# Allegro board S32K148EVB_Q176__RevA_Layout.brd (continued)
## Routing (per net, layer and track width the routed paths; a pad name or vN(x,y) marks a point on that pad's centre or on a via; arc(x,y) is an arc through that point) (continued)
PTA19/FTM4_CH1/LPUART1_RX/LPSPI: length 12.1
  TOP w0.16: U8.2 v1(78.8,67.57)
  L3_INT_1 w0.191: J6.13 81.24,71.49 78.8,69.05
  L3_INT_1 w0.203: 78.8,69.05 v1(78.8,67.57)
PTA20/FTM4_CH2/LPSPI1_SIN: length 18.1
  TOP w0.16: U8.3 v1(78.3,68.04)
  L3_INT_1 w0.191: J6.15 80.13,81.4 80.13,76.71 80.68,76.17 80.68,74.81 77.88,72.01 77.88,69.13 77.97,69.05
  L3_INT_1 w0.203: 77.97,69.05 78.3,68.71 v1(78.3,68.04)
PTA21/FTM4_CH3/FXIO_D0/LPSPI1_P: length 21.1
  TOP w0.16: U8.6 v1(76.8,67.57)
  L3_INT_1 w0.191: 80.77,69.05 80.8,69.07 81.01,69.07 82.65,70.71 82.65,81.37 J6.12
  L3_INT_1 w0.203: 80.77,69.05 80.1,68.37 80.1,68.16 79.03,67.09 77.28,67.09 v1(76.8,67.57)
PTA22/FTM4_CH4/FXIO_D1/LPSPI1_P: length 25.5
  TOP w0.16: U8.9 v1(75.3,68.04)
  L3_INT_1 w0.191: J6.9 85.21,81.4 85.21,76.97 85.48,76.7 85.48,73.04 81.49,69.05
  L3_INT_1 w0.203: v1(75.3,68.04) 75.3,67.39 75.95,66.74 79.18,66.74 80.45,68.01 80.45,68.23 80.95,68.72 81.16,68.72 81.49,69.05
PTA23/FTM4_CH6/FXIO_D2: length 29
  TOP w0.16: U8.13 v1(73.3,68.04)
  L3_INT_1 w0.191: J6.6 87.43,81.08 87.43,74.49 81.99,69.05
  L3_INT_1 w0.203: v1(73.3,68.04) 73.3,67.39 74.31,66.38 79.33,66.38 80.81,67.87 80.81,68.08 81.09,68.36 81.31,68.36 81.99,69.05
PTA24/FTM4_CH7/FXIO_D3: length 31.9
  TOP w0.16: U8.16 v1(71.79,67.57)
  L3_INT_1 w0.191: J6.3 90.29,81.4 90.29,75.28 86.11,71.1 86,71.1 85.72,70.82 85.72,70.71 83.93,68.92
  L3_INT_1 w0.203: v1(71.79,67.57) 73.34,66.03 81.04,66.03 83.93,68.92
PTA25/FTM5_CH0: length 81.2
  TOP w0.16: U8.17 v1(71.29,68.04) ; U7.10 v1(72.79,63.24)
  L6_INT_2 w0.191: 52.74,67.58 51.68,67.58 42.94,76.32 41.18,76.32 40.52,76.97 40.52,78.87 J2.2 ; v1(40.53,51.62) 40.53,52.45 37.71,55.27 37.71,61.36 39.18,62.82 v1(40.12,62.82)
  L6_INT_2 w0.203: v1(71.29,68.04) 71.29,67.39 70.64,66.74 56.32,66.74 55.94,67.12 53.21,67.12 52.74,67.58
  BOTTOM w0.16: v1(71.29,68.04) 71.29,66.07 71.78,65.58 71.78,65.33 72.79,64.32 v1(72.79,63.24)
  BOTTOM w0.406: R552.1 v1(40.53,51.62) ; J2.2 42.84,78.75 42.84,76.43 41.03,74.63 41.03,63.74 v1(40.12,62.82)
PTA26/FTM5_CH1/LPSPI1_PCS0: length 144.7
  TOP w0.16: U8.26 v1(66.79,67.57) ; U7.19 v1(68.29,62.77)
  TOP w0.406: v1(57.65,20.03) 57.65,21.24 56.83,22.06 R283.1
  L3_INT_1 w0.191: v1(80.4,32.7) 80.4,33.04 81.65,34.29 81.65,36.44 83.34,38.14 83.34,40.68 81.26,42.76 81.26,52.47 79.65,54.08 79.65,55.56 73.8,61.4 69.66,61.4 v1(68.29,62.77) ; v1(26.48,32.15) 26.48,42.42 26.83,42.76 26.83,43.16 26.48,43.51 26.48,45.6 26.08,46 26.08,46.08 v1(25.74,46.42)
  L6_INT_2 w0.191: v1(26.48,32.15) 26.48,21.77 28.35,19.9 39.08,19.9 39.64,20.46 57.21,20.46 v1(57.65,20.03)
  BOTTOM w0.16: v1(68.29,62.77) 68.29,64.73 66.79,66.23 v1(66.79,67.57)
  BOTTOM w0.191: v1(80.4,32.7) 77.48,29.78 77.48,25.36 72.15,20.03 v1(57.65,20.03)
  BOTTOM w0.203: R564.1 26.05,46.64 25.82,46.42 v1(25.74,46.42)
PTA26/FTM5_CH1/LPSPI1_PCS0_LS: length 9.6
  TOP w0.406: v1(29.81,56.59) R149.1
  TOP w0.508: v1(29.81,56.59) 29.78,56.61 29.73,56.61 29.49,56.86 TP17.1
  BOTTOM w0.203: U507.6 26.56,50.84 27.01,51.29 27.37,51.29 29.81,53.73 v1(29.81,56.59)
PTA27/FTM5_CH2/LPSPI1_SOUT/LP_1: length 4.9
  TOP w0.406: R177.1 30.29,53.4 TP22.1 31.43,53.4 v1(31.94,53.91)
  BOTTOM w0.203: U506.6 33.29,53.37 32.75,53.91 v1(31.94,53.91)
PTA27/FTM5_CH2/LPSPI1_SOUT/LPUA: length 93.6
  TOP w0.16: U7.22 v1(66.79,63.24) ; U8.29 v1(65.29,68.04)
  L3_INT_1 w0.191: v1(34.73,48.85) 35.21,48.85 35.78,49.42 37.42,49.42 39.3,51.3 39.3,51.97 40.85,53.52 42.05,53.52 46.55,58.02 v1(46.77,58.02)
  L6_INT_2 w0.191: J4.6 51.87,25.52 49.1,25.52 47.97,26.65 47.97,28.43 45.81,30.6 35.92,30.6 33.01,33.51 32.56,33.51 30.7,35.38 29.14,36.93 29.14,42.97 34.4,48.23 34.4,48.52 v1(34.73,48.85) ; v1(46.77,58.02) 48.59,58.02 52.27,61.71 52.74,61.71
  L6_INT_2 w0.203: v1(66.79,63.24) 66.79,62.59 65.35,61.15 60.85,61.15 60.38,61.62 59.36,61.62 59.19,61.45 54.45,61.45 54.2,61.71 52.74,61.71
  BOTTOM w0.16: v1(66.79,63.24) 66.79,64.7 65.29,66.2 v1(65.29,68.04)
  BOTTOM w0.203: v1(34.73,48.85) R555.1
PTA28/FTM5_CH3/LPSPI1_SCK/LPU_1: length 10.2
  TOP w0.406: R150.1 29.91,54.82 30.57,55.48 v1(30.57,55.89) 30.92,55.89 31.15,56.12 TP21.1
  BOTTOM w0.203: v1(30.57,55.89) 30.23,55.55 30.23,53.57 27.57,50.91 27.18,50.91 26.96,50.7 U507.7
PTA28/FTM5_CH3/LPSPI1_SCK/LPUAR: length 126.8
  TOP w0.16: U8.31 v1(64.29,68.04) ; U7.24 v1(65.79,63.24)
  L6_INT_2 w0.191: J4.9 54.11,22.36 43.32,22.36 42.03,23.65 42.03,26.75 40.83,27.95 35.19,27.95 34.41,28.73 34.41,31.15 32.69,32.87 32.31,32.87 30.43,34.74 27.41,37.76 v1(27.41,42.24) 27.41,43.18 27.72,43.48 28.75,43.48 32.09,46.82 32.09,51.98 31.77,52.3 31.74,52.3 30.41,53.63 29.13,53.63 27.22,55.54 27.22,56.93 29.58,59.29 30.65,59.29 32.31,57.63 33.53,57.63 39.2,63.31 41.19,63.31 41.31,63.19 50.68,63.19 v1(51.09,63.6) ; v1(64.29,68.04) 62.94,69.4 61.58,69.4 61.19,69.78 57.79,69.78 57.13,69.12 54.72,69.12 54.51,69.34 52.83,69.34 v1(51.17,71)
  BOTTOM w0.16: v1(65.79,63.24) 65.79,64.75 64.29,66.25 v1(64.29,68.04)
  BOTTOM w0.191: v1(51.17,71) 51.62,70.55 51.62,64.13 v1(51.09,63.6)
  BOTTOM w0.406: v1(27.41,42.24) 27.41,44.2 27.52,44.31 R563.1
PTA29/FTM5_CH4/LPUART2_TX/LPS_1: length 5.5
  TOP w0.406: v1(33.69,53.67) 33.66,53.71 33.08,53.71 32.27,54.52 TP25.1 30.39,54.52 R154.1
  BOTTOM w0.203: U506.7 v1(33.69,53.67)
PTA29/FTM5_CH4/LPUART2_TX/LPSPI: length 113.2
  TOP w0.16: U7.26 v1(64.79,63.24) ; U8.33 v1(63.29,68.04)
  L3_INT_1 w0.191: v1(36.32,51.34) 36.66,51.68 36.66,53.25 36.09,53.83 36.09,54.69 36.37,54.97 37.71,54.97 37.86,54.82 38.65,54.82 39.16,55.33 41.61,55.33 46.29,60.01 v1(51.24,60.01)
  L6_INT_2 w0.191: v1(36.32,51.34) 33.95,48.97 33.95,48.23 28.82,43.1 28.82,36.8 30.19,35.43 32.43,33.2 32.82,33.2 35.73,30.28 43.58,30.28 44.25,29.61 44.25,23.96 45.54,22.67 53.89,22.67 54.73,23.52 54.73,24.53 55.39,25.19 57.28,25.19 J4.12 ; 52.74,68.99 52.29,68.99 v1(51.14,70.14) ; 57.55,69.05 57.97,69.47 61.06,69.47 61.48,69.05
  L6_INT_2 w0.203: 57.55,69.05 57.25,68.74 54.61,68.74 54.36,68.99 52.74,68.99 ; 61.48,69.05 62.28,69.05 v1(63.29,68.04)
  BOTTOM w0.16: v1(63.29,68.04) 63.29,66.29 64.79,64.79 v1(64.79,63.24)
  BOTTOM w0.203: R554.1 36.74,51.04 36.54,51.24 36.54,51.34 v1(36.32,51.34)
  BOTTOM w0.406: v1(51.24,60.01) 51.24,60.59 50.51,61.33 50.51,65.4 51.14,66.04 v1(51.14,70.14)
PTA30/FTM5_CH5: length 54.6
  TOP w0.16: U8.34 v1(62.79,67.57) ; U7.27 v1(64.29,62.77)
  L3_INT_1 w0.191: 62.79,69.05 62.79,70.79 64.89,72.89 64.89,82.65 63.92,83.62 45,83.62 v1(43.69,82.31)
  L3_INT_1 w0.203: v1(62.79,67.57) 62.79,69.05
  L6_INT_2 w0.191: v1(43.69,82.31) 43.69,81.39 43.21,80.92 42.24,80.92 42.08,81.08 41.16,81.08 40.19,80.11 40.19,78.54 J2.4
  BOTTOM w0.16: v1(62.79,67.57) 62.79,66.32 64.29,64.81 v1(64.29,62.77)
PTA31/FTM5_CH6: length 40.1
  TOP w0.16: U7.33 v1(61.29,62.77) ; U8.40 v1(59.79,67.57)
  L3_INT_1 w0.191: v1(44.33,82.07) 45.01,81.4 48.81,81.4 49.65,80.56 49.65,75.4 50.7,74.36 53.43,74.36 55.97,71.82
  L3_INT_1 w0.203: v1(59.79,67.57) 59.79,70.26 58.23,71.82 55.97,71.82
  L6_INT_2 w0.191: v1(44.33,82.07) 44.33,80.14 J2.1
  BOTTOM w0.16: v1(59.79,67.57) 59.79,65.99 61.29,64.49 v1(61.29,62.77)
PTB0/SBC_LPSPI0_PCS0: length 92
  TOP w0.16: U7.78 v1(62.29,44.59)
  TOP w0.203: v1(61.8,39.78) 61.79,39.8 61.79,40.98
  BOTTOM w0.16: v1(61.8,39.78) 61.8,40.26 62.29,40.75 v1(62.29,44.59)
  BOTTOM w0.191: J2.7 37.64,78.53 37.64,82.96 36.69,83.91 26.22,83.91 24.96,82.65 24.96,71.53 39.33,57.16 39.46,57.16 46.44,50.18 46.44,48.83 46.84,48.43 46.84,46.88 52.72,41.01 54.22,41.01 57.11,38.11 59.77,38.11 59.78,38.12 60.7,38.12 60.71,38.11 60.75,38.11 61.79,39.15 61.79,39.3 61.8,39.31 v1(61.8,39.78)
PTB1/LPSPI0_SOUT: length 67.2
  TOP w0.16: 61.29,40.98 61.29,39.79 61.29,39.78 v1(61.29,39.32) ; U7.77 v1(61.79,44.12)
  L3_INT_1 w0.191: 52.74,69.05 51.56,69.05 43.12,77.49 43.12,80.02 42.07,81.07 36.08,81.07 35.11,80.09 35.11,78.54 J2.10
  L3_INT_1 w0.203: v1(61.79,44.12) 61.31,43.64 59.09,43.64 58.15,44.58 58.15,65.1 55.77,67.47 54.43,67.47 52.85,69.05 52.74,69.05
  BOTTOM w0.16: v1(61.29,39.32) 61.29,40.33 61.79,40.83 v1(61.79,44.12)
PTB2/LPSPI0_SCK: length 76.1
  TOP w0.16: U7.68 v1(58.98,46.93) ; U8.78 v1(54.65,47.93)
  L6_INT_2 w0.191: J2.16 31.36,74.99 38.44,74.99 38.5,74.93 v1(38.98,74.93)
  BOTTOM w0.16: v1(58.98,46.93) 57.99,47.93 v1(54.65,47.93)
  BOTTOM w0.191: v1(38.98,74.93) 39.31,75.27 39.31,75.46 40.51,76.65 40.51,82.97 41.16,83.62 48.68,83.62 49.33,82.97 49.33,76.84 50.32,75.85 51.36,75.85 51.76,75.45 51.76,74.83 50.34,73.4 50.34,66.46 49.75,65.88 49.75,60.96 50.36,60.36 50.36,54.93 52.95,52.33 52.95,48.99 54.01,47.93 v1(54.65,47.93)
PTB3/LPSPI0_SIN: length 72.4
  TOP w0.16: U8.73 v1(54.18,50.43) ; U7.63 v1(59.45,49.43)
  L6_INT_2 w0.191: v1(38.44,75.47) 38.11,75.8 33.08,75.8 J2.13
  BOTTOM w0.16: v1(54.18,50.43) 55.54,50.43 56.54,49.43 v1(59.45,49.43)
  BOTTOM w0.191: 52.11,74.56 52.11,75.56 51.49,76.17 50.45,76.17 49.65,76.97 49.65,83.1 48.81,83.94 41.03,83.94 40.19,83.1 40.19,76.87 39.12,75.8 38.78,75.8 v1(38.44,75.47)
  BOTTOM w0.203: 52.11,74.56 50.66,73.11 50.66,66.33 50.08,65.74 50.08,61.1 50.68,60.5 50.68,55.14 53.33,52.48 53.33,51.09 53.99,50.43 v1(54.18,50.43)
PTB4/MII_RMII_MDIO: length 104
  TOP w0.406: R268.2 v1(39.18,32.56) ; R46.2 103.71,73.62 103.31,73.23 v1(103.29,73.23)
  L6_INT_2 w0.191: v1(103.29,73.23) 103.77,73.23 107.89,69.1 107.89,56.66 102.17,50.93 100.09,50.93 99.63,50.47 99.63,45.6 85.25,31.22 78.39,31.22 78.14,31.47 60.54,31.47 60.46,31.55 57.16,31.55 56.95,31.76 51.49,31.76 51.09,31.36 39.9,31.36 39.18,32.08 v1(39.18,32.56)
PTB4/MII_RMII_MDIO/QSPI_B_IO0: length 49.5
  TOP w0.16: U7.41 v1(59.45,60.43) ; U8.49 v1(54.18,62.44)
  TOP w0.406: R227.1 36.06,42.25 36.03,42.27 v1(34.89,42.27)
  L3_INT_1 w0.191: 52.74,62.44 43.38,62.44 39.17,58.23 36.35,58.23 34.99,56.88 34.99,54.02 35.78,53.23 35.78,52.24 33.79,50.25 33.79,42.9 34.41,42.27 v1(34.89,42.27)
  L3_INT_1 w0.203: v1(54.18,62.44) 52.74,62.44
  BOTTOM w0.16: v1(59.45,60.43) 57.44,60.43 55.44,62.44 v1(54.18,62.44)
PTB4/MII_RMII_MDIO/QSPI_B_IO0_1: length 4.1
  TOP w0.279: R268.1 38.7,34.81 v1(38.7,35.41) 38.7,35.93 38.84,36.07 38.84,36.08 38.84,36.08 U14.2
  BOTTOM w0.279: v1(38.7,35.41) 38.7,34.81 R268.1
PTB4/MII_RMII_MDIO/QSPI_B_IO0__: length 3.3
  TOP w0.279: v1(37.98,41.39) 38.35,41.02 38.39,41.02 38.84,40.57 U14.13
  TOP w0.406: v1(37.98,41.39) 37.96,41.39 38.04,41.46 R227.2
  BOTTOM w0.279: v1(37.98,41.39) 37.96,41.39 38.04,41.47 38.04,41.85 R572.2
PTB5/ENET_MII_RMII_MDC: length 104.9
  TOP w0.279: U22.2 65.75,34.52 65.76,34.5 65.76,33.98 66,33.74 v1(66.52,33.74) R273.2
  TOP w0.406: R38.2 103.52,74.64 102.6,73.72 v1(102.6,73.14)
  L6_INT_2 w0.191: v1(66.52,33.74) 68.52,33.74 68.99,34.22 78.8,34.22 79.32,33.7 79.71,33.7 80.81,34.8 83.44,34.8 83.45,34.8 84.11,34.8 84.39,35.08 84.39,35.74 91.47,42.82 91.47,46.55 92.72,47.81 92.72,47.83 98.52,53.62 100.17,53.62 101.01,54.46 101.01,54.59 104.06,57.64 104.06,60.77 102.51,62.32 102.51,64.01 103.16,64.66 103.16,67.78 102.6,68.34 102.6,68.5 102.51,68.59 101.64,68.59 101.55,68.68 101.55,68.81 101.64,68.91 102.51,68.91 102.6,69 102.6,69.13 102.51,69.23 101.64,69.23 101.55,69.32 101.55,69.45 101.64,69.54 102.51,69.54 102.6,69.64 102.6,69.77 102.51,69.86 101.64,69.86 101.55,69.95 101.55,70.08 101.64,70.18 102.51,70.18 102.6,70.27 102.6,70.59 102.51,70.68 101.22,70.68 101.13,70.59 101.13,70.13 101.04,70.04 100.91,70.04 100.81,70.13 100.81,70.59 100.72,70.68 100.59,70.68 100.5,70.59 100.5,70.13 100.4,70.04 100.27,70.04 100.18,70.13 100.18,70.59 100.09,70.68 99.95,70.68 99.86,70.59 99.86,70.13 99.77,70.04 99.64,70.04 99.54,70.13 99.54,70.59 99.45,70.68 98.68,70.68 98.59,70.77 98.59,70.91 98.68,71 99.41,71 99.51,71.09 99.51,71.88 99.6,71.97 99.73,71.97 99.82,71.88 99.82,71.09 99.92,71 100.99,71 101.08,71.09 101.08,71.41 100.99,71.5 100.33,71.5 100.23,71.6 100.23,71.73 100.33,71.82 100.99,71.82 101.08,71.91 101.08,72.04 100.99,72.14 100.33,72.14 100.23,72.23 100.23,72.36 100.33,72.45 100.99,72.45 101.08,72.55 101.08,73.25 101.17,73.34 101.31,73.34 101.4,73.25 101.4,71.09 101.49,71 101.62,71 101.72,71.09 101.72,73.25 101.81,73.34 101.94,73.34 102.03,73.25 102.03,71.09 102.13,71 102.51,71 102.6,71.09 102.6,71.3 102.7,71.4 103.04,71.4 103.13,71.49 103.13,71.62 103.04,71.71 102.7,71.71 102.6,71.81 102.6,71.94 102.7,72.03 103.04,72.03 103.13,72.12 103.13,72.26 103.04,72.35 102.7,72.35 102.6,72.44 v1(102.6,73.14)
PTB5/MII_RMII_MDC: length 89.2
  TOP w0.16: U8.48 v1(54.65,62.94) ; U7.40 v1(58.98,60.93)
  L3_INT_1 w0.191: v1(54.65,62.94) 54.65,63.06 54.15,63.56 51.74,63.56 v1(51.09,62.91)
  L6_INT_2 w0.191: v1(58.64,32.37) 57.52,32.37 57.12,32.77 56.7,32.77 56.01,32.08 51.36,32.08 50.96,31.68 40.4,31.68 39.66,32.43 39.66,32.76 39.38,33.04 36.63,33.04 35.18,34.49 32.48,34.49 29.78,37.2 29.78,41.11 35.36,46.7 38.73,46.7 40.77,48.73 40.77,50.1 41,50.33 41,52.43 39.68,53.75 39.68,54.89 39.4,55.17 39.38,55.17 38.63,55.92 38.63,60.75 40.14,62.27 50.44,62.27 v1(51.09,62.91)
  BOTTOM w0.16: v1(58.98,60.93) 57.42,60.93 55.41,62.94 v1(54.65,62.94)
  BOTTOM w0.406: R604.1 v1(58.64,32.37)
PTB5/MII_RMII_MDC__A: length 3.6
  TOP w0.279: v1(60.6,33.93) 60.6,34.1 60.83,34.34 60.83,34.43 60.92,34.52 U22.13
  BOTTOM w0.406: R604.2 60.19,33.93 v1(60.6,33.93) 60.99,33.54 R603.2
PTB6_XTAL: length 16.5
  TOP w0.16: U8.25 v1(67.29,68.04) ; U7.18 v1(68.79,63.24)
  TOP w0.229: C3.1 Y1.2 66.53,71 67.02,70.51 R64.2 ; R64.2 R76.2 67.02,68.32 v1(67.29,68.04) ; R64.2 66.26,70.32 66,70.06 R76.1
  BOTTOM w0.16: v1(68.79,63.24) 68.79,64.73 67.29,66.23 v1(67.29,68.04)
PTB7_EXTAL: length 17.2
  TOP w0.16: U8.24 v1(67.79,67.57) ; U7.17 v1(69.29,62.77)
  TOP w0.229: R78.1 69.05,69.96 68.69,70.32 R64.1 ; R64.1 R78.2 68.03,68.74 67.79,68.5 v1(67.79,67.57) ; R64.1 68.53,70.81 Y1.1 C4.1
  BOTTOM w0.16: v1(67.79,67.57) 67.79,66.29 69.29,64.79 v1(69.29,62.77)
PTB8/FTM3_CH0/SAI1_BCLK: length 64.7
  TOP w0.16: U8.136 v1(82.91,44.42) ; U7.111 v1(78.1,45.93)
  TOP w0.406: R318.1 55.31,13.65 63.18,13.65 J5.4
  L3_INT_1 w0.203: v1(78.1,45.93) 78.58,45.93 78.96,45.56 78.96,41.8 80.57,40.18 80.57,39.19 79.07,37.69 79.07,35.11 78.6,34.64 77.51,34.64 72.5,29.63 72.5,28.71 73.36,27.85 74.94,27.85 J5.4
  BOTTOM w0.16: v1(82.91,44.42) 80.72,44.42 79.21,45.93 v1(78.1,45.93)
PTB9/FTM3_CH1/LPI2C0_SCLS: length 107.2
  TOP w0.16: U8.133 82.31,42.92 82.33,42.9 v1(82.8,42.9) ; U7.109 v1(78.1,44.93)
  TOP w0.203: v1(82.8,42.9) 83.52,42.9 83.55,42.92 83.93,42.92
  TOP w0.406: 83.93,42.92 84.76,42.92 86.93,45.1 89.32,45.1 89.73,45.5 v1(89.73,50.12) R192.1 ; R319.1 v1(55.59,12.35)
  L3_INT_1 w0.191: v1(55.59,12.35) 56.05,11.9 62.1,11.9 75.29,25.08 76.18,25.08 77.27,26.17 77.27,27.22 78.11,28.06 79.16,28.06 79.81,28.71 79.81,29.93 84.84,34.95 84.84,36.62 84.35,37.12 84.35,37.72 84.51,37.88 84.51,42.03 83.93,42.61
  L3_INT_1 w0.203: v1(82.8,42.9) 83.64,42.9 83.93,42.61
  L6_INT_2 w0.191: J6.10 85.81,75.4 v1(91.22,75.4)
  BOTTOM w0.16: v1(78.1,44.93) 80.21,42.82 82.25,42.82 82.33,42.9 v1(82.8,42.9)
  BOTTOM w0.406: v1(91.22,75.4) 90.51,74.69 90.51,53.07 89.17,51.73 89.17,50.68 v1(89.73,50.12)
PTB10/FTM3_CH2/LPI2C0_SDAS: length 153.3
  TOP w0.16: 78.8,40.98 v1(78.8,39.32) ; U7.108 77.29,43.99 77.46,44.16 77.46,44.16 v1(77.48,44.16)
  TOP w0.406: R315.1 v1(45.43,12.14) ; R187.1 v1(89.75,51.14)
  L3_INT_1 w0.191: v1(45.43,12.14) 46.12,12.83 52.32,12.83 53.57,11.58 63.7,11.58 64.93,12.81 66.82,12.81 67.77,11.85 81.19,11.85 90.28,20.95 90.28,28.56 90.29,28.58 90.29,29.76 90.28,29.77 90.28,50.61 v1(89.75,51.14)
  L6_INT_2 w0.191: v1(89.75,51.14) 90.2,50.69 90.2,48.43 89.21,47.44 89.21,43.9 85.29,39.99 83.93,39.99
  L6_INT_2 w0.203: v1(78.8,39.32) 79.14,38.98 79.67,38.98 80.68,39.99 83.93,39.99
  BOTTOM w0.16: v1(78.8,39.32) 78.8,42.83 v1(77.48,44.16)
  BOTTOM w0.406: v1(89.75,51.14) 91.73,53.12 91.73,70.95 92.62,71.84 92.62,80.47 91.91,81.19 85.82,81.19 85.1,80.47 85.1,78.65 J6.7
PTB11/FTM3_CH3/LPI2C0_HREQ: length 86.9
  TOP w0.16: U7.107 v1(76.79,44.15) ; 77.3,40.98 v1(77.3,39.79)
  L3_INT_1 w0.191: J2.17 27.82,78.87 27.82,76.97 31.56,73.24 45.11,73.24 52.69,65.66 52.74,65.66
  L3_INT_1 w0.203: v1(76.79,44.15) 76.45,43.81 76.45,43.78 74.53,41.86 58.35,41.86 56.37,43.85 56.37,64.36 55.07,65.66 52.74,65.66
  BOTTOM w0.16: v1(77.3,39.79) 77.3,43.62 77.12,43.8 77.12,43.83 v1(76.79,44.15)
PTB12/FTM0_CH0/FTM3_FLT2/CAN2_R: length 95.5
  TOP w0.16: 72.8,40.98 v1(72.8,39.32) ; U7.98 v1(72.29,44.59)
  L3_INT_1 w0.191: J2.29 20.17,78.55 26.52,78.55 27.8,79.84 27.8,80.41 28.46,81.07 29.37,81.07 30.35,80.09 30.35,76.99 33.76,73.57 45.23,73.57 51.94,66.86 52.74,66.86
  L3_INT_1 w0.203: v1(72.29,44.59) 72.29,43.94 70.57,42.22 58.5,42.22 56.72,43.99 56.72,64.51 55.21,66.02 53.59,66.02 52.74,66.86
  BOTTOM w0.16: v1(72.29,44.59) 72.29,40.91 72.8,40.41 v1(72.8,39.32)
PTB13/FTM0_CH1/FTM3_FLT1/CAN2_T: length 83.1
  TOP w0.16: U7.97 v1(71.79,44.12) ; 72.29,40.98 v1(72.29,39.79)
  BOTTOM w0.16: 71.79,40.29 v1(72.29,39.79)
  BOTTOM w0.191: J2.26 22.41,78.86 22.41,75.1 23.18,74.32 23.18,72.86 39.2,56.84 39.31,56.84 46.11,50.04 46.11,48.7 46.52,48.29 ; v1(72.29,39.79) 72.29,39.01 72.62,38.68 72.62,38.47 72.66,38.43 72.66,38.04 72.62,38 72.62,37.93 72.32,37.62 65.44,37.62 64.94,37.11 63.05,37.11 62.76,37.41 60.96,37.41 60.57,37.8 59.91,37.8 59.9,37.79 56.94,37.79 54.08,40.65
  BOTTOM w0.203: 46.52,48.29 46.52,46.72 52.59,40.65 54.08,40.65 ; v1(71.79,44.12) 71.79,40.29
PTB14/FTM0_CH2/LPSPI1_SCK/ADC1_: length 32.6
  TOP w0.16: 71.29,40.98 v1(71.29,39.79) ; U7.96 v1(71.29,44.59)
  TOP w0.203: v1(71.29,39.79) 71.29,39.02 71.59,38.72 73.16,38.72
  TOP w0.406: J5.15 88.02,32.55 83.64,32.55 80.17,36.03 75.86,36.03 73.16,38.72
  BOTTOM w0.16: v1(71.29,39.79) 71.29,40.25 71.29,40.25 v1(71.29,44.59)
PTB15/FTM0_CH3/LPSPI1_SIN/ADC1_: length 37.3
  TOP w0.16: 70.79,40.98 v1(70.79,39.32) ; U7.95 v1(70.79,44.12)
  TOP w0.203: v1(70.79,39.32) 70.79,38.83 71.01,38.62
  TOP w0.406: J5.17 92.7,27.93 88.4,27.93 88.37,27.95 88.36,27.95 87.64,28.66 87.64,28.68 87.59,28.73 87.59,30.26 86.53,31.33 78.17,31.33 71.31,38.19 71.31,38.32 71.01,38.62
  BOTTOM w0.16: v1(70.79,39.32) 70.79,39.78 70.79,39.78 v1(70.79,44.12)
PTB16: length 10.2
  TOP w0.16: U7.94 v1(70.29,44.61)
  TOP w0.203: 70.29,40.98 v1(70.29,39.79)
  BOTTOM w0.16: v1(70.29,44.61) 70.29,40.25 70.29,40.25 v1(70.29,39.79)
  BOTTOM w0.203: 70.5,38.62 70.5,38.93 70.29,39.14 v1(70.29,39.79)
  BOTTOM w0.406: v1(70.29,44.61) 70.27,44.64 R634.2 ; 70.5,38.62 70.5,38.31 R635.2
PTB16/FTM0_CH4/LPSPI1_SOUT/ADC1: length 31.4
  TOP w0.203: v1(81.8,38.82) 81.8,38.62
  TOP w0.406: J5.19 93.76,31.89 90.29,31.89 89.07,33.11 83.97,33.11 81.88,35.2 81.88,38.26 81.8,38.34 81.8,38.62
  L6_INT_2 w0.191: 73.04,38.62 72.66,38.24 v1(72.19,38.24)
  L6_INT_2 w0.203: v1(81.8,38.82) 81.6,38.62 73.05,38.62 73.04,38.62
  BOTTOM w0.406: R635.1 v1(72.19,38.24)
PTB17/FTM0_CH5/LPSPI1_PCS3/FTM5: length 116.9
  TOP w0.16: U7.93 v1(69.79,44.12) ; 69.29,40.98 v1(69.29,39.32)
  TOP w0.406: v1(69.38,30.92) 69.79,30.51 69.79,22.95 65.87,19.04 v1(65.29,19.04) ; R287.1 v1(48.81,19.72)
  L3_INT_1 w0.191: J2.14 32.57,78.86 32.57,77.3 35.97,73.9 45.35,73.9 51.87,67.38 52.74,67.38 ; 69.37,38.62 70.03,37.95 70.03,35.42 69.38,34.77 v1(69.38,30.92)
  L3_INT_1 w0.203: v1(69.29,39.32) 69.29,38.69 69.37,38.62 ; v1(69.79,44.12) 68.24,42.57 58.65,42.57 57.08,44.14 57.08,64.66 55.36,66.37 53.75,66.37 52.74,67.38
  L6_INT_2 w0.191: v1(65.29,19.04) 57.09,19.04 56.06,20.06 49.14,20.06 v1(48.81,19.72)
  BOTTOM w0.16: v1(69.79,44.12) 69.79,39.82 v1(69.29,39.32)
PTB18/FTM5_CH7/LPSPI1_PCS1/ADC0: length 50.3
  TOP w0.16: v1(58.94,68.67) 58.46,68.19 58.33,68.19 58.31,68.16 58.31,68.01 58.28,67.98 U8.43 ; U7.36 v1(59.79,63.24)
  L3_INT_1 w0.191: J2.11 32.89,81.08 32.89,82.97 33.54,83.62 42.08,83.62 42.73,82.97 42.73,82.6 44.25,81.08 48.68,81.08 49.33,80.43 49.33,75.27 50.6,74 53.34,74 55.65,71.69 55.65,71.68 55.83,71.49 57.77,71.49 58.94,70.32 58.94,69.05
  L3_INT_1 w0.203: 58.94,69.05 v1(58.94,68.67)
  BOTTOM w0.16: v1(58.94,68.67) 58.46,68.19 58.33,68.19 58.31,68.16 58.31,64.72 v1(59.79,63.24)
PTB19/FTM5_CH7: length 27.8
  TOP w0.16: v1(57.85,68.16) 57.85,67.7 57.78,67.63 U8.44
  BOTTOM w0.203: 58.15,69.05 57.86,68.77 57.86,68.66 57.85,68.64 v1(57.85,68.16)
  BOTTOM w0.406: 58.15,69.05 58.32,69.23 58.46,69.23 67.02,77.78 67.02,82.71 68.04,83.73 72.4,83.73 J6.24
PTB20/FTM6_CH0/ADC0_SE17: length 103.9
  TOP w0.16: U7.37 59.45,62.43 v1(59.62,62.26) ; v1(53.96,64.48) 54.73,64.48 54.78,64.44 U8.45
  TOP w0.406: R265.1 57.87,33.94 v1(57.87,33.3)
  L3_INT_1 w0.191: 55.29,54.1 55.29,47.89 54.85,47.45 54.5,47.45 52.93,45.88 52.93,45.44 53.6,44.77 53.6,43.21 53.94,42.87 53.94,42.07 51.63,39.76 51.63,38.31 53.76,36.18 53.76,36.01 56.81,32.97 57.54,32.97 v1(57.87,33.3)
  L3_INT_1 w0.203: 55.29,54.1 55.29,63.95 54.76,64.48 v1(53.96,64.48)
  L6_INT_2 w0.191: J6.1 90.13,78.7 90.13,83.12 89.4,83.86 68.19,83.86 66.03,81.7 v1(66.03,80.5)
  BOTTOM w0.16: v1(53.96,64.48) 57.4,64.48 v1(59.62,62.26)
  BOTTOM w0.203: v1(53.96,64.48) 55.61,66.13 55.61,67.37 57.3,69.05
  BOTTOM w0.406: v1(66.03,80.5) 66.03,77.78 57.3,69.05
PTB20/FTM6_CH0/ADC0_SE17__A: length 3.7
  TOP w0.279: v1(60.31,34.55) 60.31,34.73 60.6,35.02 U22.12
  TOP w0.406: R265.2 60.06,34.48 60.13,34.55 v1(60.31,34.55)
  BOTTOM w0.406: R597.2 60.9,34.48 60.82,34.55 v1(60.31,34.55)
PTB20/FTM6_CH0/ENET_INT: length 104.9
  TOP w0.279: U22.3 65.86,35.02 v1(66.46,34.42) 66.46,34.42 66.46,34.4 66.72,34.66 66.8,34.66 66.9,34.76 R263.2
  TOP w0.406: v1(102.31,76.44) 102.31,77.11 102.88,77.68 R5.2
  L6_INT_2 w0.191: v1(102.31,76.44) 99.92,74.05 99.33,74.05 99.23,73.96 99.23,73.42 99.14,73.33 99.01,73.33 98.92,73.42 98.92,73.96 98.82,74.05 98.45,74.05 97.81,73.41 97.81,73.28 98.44,72.65 98.44,72.52 98.35,72.43 98.22,72.43 97.59,73.06 97.45,73.06 97.36,72.96 97.36,72.83 97.99,72.2 97.99,72.07 97.9,71.98 97.77,71.98 97.14,72.61 97.01,72.61 96.91,72.51 96.91,72.38 97.54,71.75 97.54,71.62 97.45,71.53 97.32,71.53 96.69,72.16 96.56,72.16 95.68,71.28 95.68,70.13 98.63,67.18 98.95,67.18 99.04,67.27 99.04,67.97 98.95,68.07 98.38,68.07 98.29,68.16 98.29,68.29 98.38,68.38 98.95,68.38 99.04,68.48 99.04,69.01 99.13,69.1 99.26,69.1 99.36,69.01 99.36,67.27 99.45,67.18 99.58,67.18 99.67,67.27 99.67,69.01 99.77,69.1 99.9,69.1 99.99,69.01 99.99,67.27 100.08,67.18 100.22,67.18 100.31,67.27 100.31,69.01 100.4,69.1 100.53,69.1 100.63,69.01 100.63,68.27 100.72,68.18 102.13,68.18 102.22,68.09 102.22,67.96 102.13,67.86 100.72,67.86 100.63,67.77 100.63,67.27 100.72,67.18 101.78,67.18 102.48,66.48 102.48,65.62 102.19,65.33 102.19,62.16 103.75,60.61 103.75,57.77 100.69,54.72 100.69,54.59 100.04,53.94 98.39,53.94 92.41,47.96 92.41,47.94 91.15,46.69 91.15,43.15 85.05,37.05 84.02,37.05 83.95,37.11 83.3,37.11 82.56,36.37 82.28,36.37 81.34,35.43 80.32,35.43 79.54,34.65 68.84,34.65 68.61,34.42 v1(66.46,34.42)
PTB21/FTM6_CH1/ADC0_SE18: length 49.4
  TOP w0.16: v1(54.57,63.99) 54.62,63.99 54.62,63.99 54.68,63.94 U8.46 ; U7.38 v1(58.98,61.93)
  L3_INT_1 w0.191: J6.4 88.86,74.34 85.94,71.42 85.87,71.42 85.4,70.95 85.4,70.88 81.05,66.53 v1(80.3,66.53)
  L6_INT_2 w0.203: v1(54.57,63.99) 54.78,64.2 77.18,64.2 79.52,66.53 v1(80.3,66.53)
  BOTTOM w0.16: v1(58.98,61.93) 56.93,63.99 v1(54.57,63.99)
PTB22/FTM6_CH2/MII_CRS/LPUART1_: length 55.3
  TOP w0.16: U7.58 v1(58.98,51.93) ; U8.66 v1(54.65,53.93)
  L3_INT_1 w0.191: v1(54.65,53.93) 50.76,53.93 47.56,50.73 47.56,45.36 45.66,43.47 45.66,39.92 46.74,38.84 46.74,37.27 47.28,36.73 47.28,34.95 44.46,32.13 44.46,28.94 43.58,28.06 31.87,28.06 J3.5
  BOTTOM w0.16: v1(54.65,53.93) 55.43,53.93 57.43,51.93 v1(58.98,51.93)
PTB23/FTM6_CH3/LPUART1_RX/MII_C: length 59.3
  TOP w0.16: U7.60 v1(58.98,50.93) ; U8.68 v1(54.65,52.93)
  TOP w0.406: v1(47.28,27.98) 46.21,27.98 46.19,27.95 29.22,27.95 J3.2
  L3_INT_1 w0.191: v1(47.28,27.98) 47.37,28.06 47.37,33.04 48.71,34.38 48.71,35.14 47.97,35.88 47.97,36.93 47.37,37.53 47.37,39.11 46.92,39.56 46.92,40.62 48.26,41.96 48.26,50.53 50.66,52.93 v1(54.65,52.93)
  BOTTOM w0.16: v1(58.98,50.93) 57.32,50.93 55.32,52.93 v1(54.65,52.93)
PTB24/FTM6_CH4: length 38.3
  TOP w0.16: U8.69 v1(54.18,52.43)
  BOTTOM w0.203: J1.18 51.88,83.63 53.76,83.63 54.42,82.97 54.42,75.18 52.44,73.2 52.44,68.15 52.39,68.1 52.39,67.81 52.39,63.76 52.26,63.64 52.26,54.65 54.18,52.73 v1(54.18,52.43)
PTB25/FTM6_CH5/LPSPI2_PCS0/ADC0: length 124.2
  TOP w0.16: U7.62 v1(58.98,49.93) ; U8.71 v1(54.18,51.43)
  TOP w0.406: v1(40.6,21.26) 40.6,21.84 41.87,23.11 41.87,25.36 J3.17 ; R218.1 v1(99.4,41.74)
  L3_INT_1 w0.191: 52.74,50.15 48.58,45.98 48.58,41.79 47.24,40.45 47.24,39.69 47.69,39.24 47.69,37.66 48.29,37.06 48.29,36.01 49.03,35.27 49.03,34.25 47.76,32.98 47.76,27.78 47.48,27.5 46.77,27.5 46.54,27.73 41.7,27.73 J3.17
  L3_INT_1 w0.203: v1(54.18,51.43) 53.46,50.71 53.3,50.71 52.74,50.15
  L6_INT_2 w0.191: v1(40.6,21.26) 88.85,21.26 92.65,25.05 92.65,34.99 v1(99.4,41.74)
  BOTTOM w0.16: v1(54.18,51.43) 55.3,51.43 56.8,49.93 v1(58.98,49.93)
PTB26/FTM6_CH6: length 35.1
  TOP w0.16: U8.72 v1(54.65,50.93)
  BOTTOM w0.203: J1.15 52.18,81.39 52.18,76.49 52.44,76.24 52.44,73.95 52.11,73.62 52.11,68.29 52.06,68.24 52.06,63.94 51.93,63.81 51.93,63.77 51.93,63.5 51.93,63.5 51.93,54.47 53.69,52.71 53.69,51.24 54,50.93 v1(54.65,50.93)
PTB27/FTM6_CH7/LPSPI2_SOUT/ADC0: length 135.9
  TOP w0.16: U7.64 v1(58.98,48.93) ; U8.74 v1(54.65,49.93)
  TOP w0.406: R221.1 v1(102.45,41.74)
  L3_INT_1 w0.191: J3.11 36.79,25.36 36.79,23.81 37.7,22.9 47.33,22.9 47.93,23.5 47.93,23.84 49.35,25.26 49.35,31.97 50.99,33.61 50.99,41.68
  L3_INT_1 w0.203: v1(54.65,49.93) 54.22,49.5 54.22,49.37 53.7,48.85 53.7,47.72 53.78,47.63 53.78,47.23 52.57,46.01 52.57,45.31 53.25,44.62 53.25,43.94 50.99,41.68
  L6_INT_2 w0.191: v1(102.45,41.74) 102.45,41.85 101.76,42.54 99.34,42.54 99.34,42.54 99.07,42.54 90.15,33.62 89.97,33.43 89.97,31.85 87.75,29.63 87.75,23.05 86.73,22.04 41.1,22.04 39.49,23.65 39.49,24.66 38.64,25.52 36.63,25.52 J3.11
  BOTTOM w0.16: v1(58.98,48.93) 56.53,48.93 55.53,49.93 v1(54.65,49.93)
PTB28/FTM7_CH0/LPSPI2_SIN/ADC0_: length 148.3
  TOP w0.16: v1(53.73,49.57) 54.19,49.57 54.33,49.43 U8.75 ; U7.65 v1(59.45,48.43)
  TOP w0.406: v1(100.42,50.14) R183.1 ; v1(38.93,21.24) 38.34,21.24 36.84,22.74 36.84,25.41 J3.14
  L3_INT_1 w0.191: J3.14 39.16,25.53 46.14,25.53 48.08,27.47 48.08,32.84 49.4,34.17 49.4,36.42 48.38,37.44 48.38,40.46 49.23,41.31 49.23,45.06 52.74,48.58
  L3_INT_1 w0.203: 52.74,48.58 v1(53.73,49.57)
  L6_INT_2 w0.191: v1(100.42,50.14) 104.96,45.6 104.96,44.77 104.9,44.71 104.9,44.31 104.96,44.25 104.96,26.93 98.74,20.71 57.41,20.71 57.34,20.78 39.87,20.78 39.4,21.24 v1(38.93,21.24)
  BOTTOM w0.16: v1(53.73,49.57) 54.19,49.57 54.33,49.43 55.4,49.43 56.39,48.43 v1(59.45,48.43)
PTB29/FTM7_CH1/LPSPI2_SCK/ADC0_: length 152
  TOP w0.16: U8.79 54.28,47.43 54.28,47.43 v1(53.3,47.43) ; U7.69 v1(59.45,46.43)
  TOP w0.406: v1(101.83,50.15) 101.43,50.54 R184.1
  L3_INT_1 w0.191: 52.74,46.87 49.54,43.67 49.54,41.17 49.33,40.97 49.33,37.25 49.72,36.86 49.72,34.02 48.39,32.69 48.39,27.34 46.27,25.21 37.92,25.21 36.82,26.32 36.82,26.89 35.98,27.73 34.08,27.73 J3.8
  L3_INT_1 w0.203: 52.74,46.87 v1(53.3,47.43)
  L6_INT_2 w0.191: v1(101.83,50.15) 101.36,50.61 100.22,50.61 99.94,50.33 99.94,49.94 102.2,47.69 102.27,47.69 103.16,46.8 103.16,41.77 102.65,41.27 102.25,41.27 101.97,41.55 101.97,41.88 101.63,42.22 99.21,42.22 90.28,33.3 90.28,23.76 88.25,21.72 83.59,21.72 83.58,21.72 40.97,21.72 39.17,23.52 39.17,24.53 38.5,25.2 34.41,25.2 J3.8
  BOTTOM w0.16: v1(59.45,46.43) 57.5,46.43 56.5,47.43 v1(53.3,47.43)
PTB30/FTM7_CH2: length 48.4
  TOP w0.16: U8.80 v1(54.65,46.93)
  L3_INT_1 w0.191: J1.6 59.58,81.16 59.58,77.05 58.84,76.31 52.35,76.31 v1(51.29,75.25)
  BOTTOM w0.191: v1(54.65,46.93) 53.13,46.93 52.57,47.49 52.57,50.8 52.57,50.8 52.57,51.99 52.57,51.99 52.57,52.12 50.02,54.67 50.02,59.61 49.43,60.2 49.43,66.07 50,66.64 50,73.96 v1(51.29,75.25)
PTB31/FTM7_CH3: length 53.3
  TOP w0.16: U8.82 v1(54.65,45.92)
  L3_INT_1 w0.191: v1(50.45,75.28) 51.05,74.67 53.56,74.67 54.03,74.2 59.27,74.2 62.14,77.08 62.14,81.19 J1.3
  BOTTOM w0.191: v1(54.65,45.92) 54.01,45.92 53.35,46.58 52.99,46.58 50.58,48.99 50.58,49.82 49.7,50.7 49.7,59.48 49.12,60.07 49.12,66.2 49.68,66.77 49.68,74.51 v1(50.45,75.28)
PTC0/MII_RMII_RXD1: length 103.4
  TOP w0.406: R277.2 v1(56.92,32.29) ; R63.2 v1(103.61,70.57)
  L6_INT_2 w0.191: v1(103.61,70.57) 104.09,70.09 104.22,70.09 105.27,71.14 105.4,71.14 105.5,71.05 105.5,70.91 104.45,69.86 104.45,69.73 104.54,69.64 104.67,69.64 105.72,70.69 105.85,70.69 105.95,70.6 105.95,70.47 104.89,69.41 104.89,69.28 104.99,69.19 105.12,69.19 106.17,70.24 106.3,70.24 106.39,70.15 106.39,70.02 105.34,68.97 105.34,68.83 105.44,68.74 105.57,68.74 106.62,69.79 106.75,69.79 106.84,69.7 106.84,69.57 105.79,68.52 105.79,68.39 105.89,68.29 106.02,68.29 107.07,69.34 107.2,69.34 107.29,69.25 107.29,69.12 106.24,68.07 106.24,67.94 107.58,66.6 107.58,63.93 107.48,63.84 106.46,63.84 106.36,63.75 106.36,63.62 106.46,63.52 107.48,63.52 107.58,63.43 107.58,63.3 107.48,63.21 106.46,63.21 106.36,63.11 106.36,62.98 106.46,62.89 107.48,62.89 107.58,62.8 107.58,62.66 107.48,62.57 106.46,62.57 106.36,62.48 106.36,62.35 106.46,62.25 107.48,62.25 107.58,62.16 107.58,56.79 102.03,51.25 99.96,51.25 99.31,50.6 99.31,45.73 85.11,31.54 79.52,31.54 79.27,31.79 60.67,31.79 60.59,31.87 57.35,31.87 v1(56.92,32.29)
PTC0/MII_RMII_RXD1/QSPI_B_RWD_1: length 4.2
  TOP w0.229: U16.13 49.18,35.41 48.57,34.81 v1(47.92,34.81) 47.91,34.81 48.09,34.99 48.09,35.65
  BOTTOM w0.229: 48.09,35.65 48.09,34.99 47.91,34.81 v1(47.92,34.81)
PTC0/MII_RMII_RXD1/QSPI_B_RWDS: length 43.7
  TOP w0.16: U8.61 v1(54.18,56.43) ; U7.53 v1(59.45,54.43)
  TOP w0.406: R259.1 v1(45.68,35.65)
  L3_INT_1 w0.191: 52.74,55.87 47.85,55.87 45.42,53.43 44.37,53.43 42.04,51.1 42.04,48.71 41.28,47.95 41.28,42.28 41.78,41.79 41.78,41.11 41.15,40.49 41.15,39.43 42.58,38 43.33,38 v1(45.68,35.65)
  L3_INT_1 w0.203: 52.74,55.87 53.61,55.87 v1(54.18,56.43)
  BOTTOM w0.16: v1(59.45,54.43) 57.76,54.43 55.76,56.43 v1(54.18,56.43)
PTC0/MII_RMII_RXD1/QSPI_B_RWDS_: length 4.7
  TOP w0.279: U16.2 54.12,35.41 54.32,35.21 v1(54.32,34.61)
  TOP w0.406: R277.1 55.71,33.77 55.17,33.77 54.74,34.2 54.73,34.2 v1(54.32,34.61)
  BOTTOM w0.406: R598.2 54.3,34.63 v1(54.32,34.61)
PTC1/MII_RMII_RXD0: length 104.6
  TOP w0.406: R74.2 v1(103.19,69.56) ; v1(57.21,33.56) 57.14,33.56 56.6,34.1 R264.2
  L6_INT_2 w0.191: v1(57.21,33.56) 57.43,33.78 58.95,33.78 60.23,32.5 60.86,32.5 60.93,32.43 79.53,32.43 79.78,32.17 83.8,32.17 92.42,40.79 92.42,46.16 93.68,47.42 93.68,47.43 98.47,52.23 100.13,52.23 101.96,54.07 101.96,54.19 105.02,57.25 105.02,60.02 105.11,60.12 107.11,60.12 107.2,60.21 107.2,60.34 107.11,60.43 105.11,60.43 105.02,60.53 105.02,60.66 105.11,60.75 107.11,60.75 107.2,60.84 107.2,60.98 107.11,61.07 105.11,61.07 105.02,61.16 105.02,61.29 105.11,61.39 107.11,61.39 107.2,61.48 107.2,61.61 107.11,61.7 105.11,61.7 105.02,61.8 105.02,64.15 104.92,64.24 103.57,64.24 103.47,64.33 103.47,64.47 103.57,64.56 104.92,64.56 105.02,64.65 105.02,64.78 104.92,64.88 103.57,64.88 103.47,64.97 103.47,65.1 103.57,65.19 104.92,65.19 105.02,65.29 105.02,65.42 104.92,65.51 103.57,65.51 103.47,65.6 103.47,65.74 103.57,65.83 104.92,65.83 105.02,65.92 105.02,66.05 104.92,66.15 103.57,66.15 103.47,66.24 103.47,66.37 103.57,66.46 104.92,66.46 105.02,66.56 105.02,66.69 104.92,66.78 103.57,66.78 103.47,66.87 103.47,67.01 103.57,67.1 104.92,67.1 105.02,67.19 105.02,67.73 v1(103.19,69.56)
PTC1/MII_RMII_RXD0/QSPI_B_SCK: length 45.8
  TOP w0.16: U7.52 v1(58.98,54.93) ; U8.60 v1(54.65,56.93)
  TOP w0.406: R253.1 46.57,36.66 v1(46.16,36.26)
  L3_INT_1 w0.191: v1(46.16,36.26) 46.16,35.46 45.88,35.17 45.42,35.17 42.91,37.68 42.45,37.68 40.84,39.3 40.84,40.63 41.46,41.25 41.46,41.65 40.5,42.61 40.5,47.83 39.8,48.53 39.8,49.75 46.96,56.91 52.72,56.91 52.74,56.93
  L3_INT_1 w0.203: 52.74,56.93 v1(54.65,56.93)
  BOTTOM w0.16: v1(54.65,56.93) 55.76,56.93 57.77,54.93 v1(58.98,54.93)
PTC1/MII_RMII_RXD0/QSPI_B_SCK_1: length 3.3
  TOP w0.229: 48.09,36.66 48.34,36.66 v1(48.93,36.07) 49.09,35.91 U16.12
  BOTTOM w0.229: 48.09,36.66 48.34,36.66 v1(48.93,36.07)
PTC1/MII_RMII_RXD0/QSPI_B_SCK__: length 4.4
  TOP w0.279: U16.3 54.54,35.91 v1(54.78,35.67) 54.78,35.44 R264.1
  BOTTOM w0.279: v1(54.78,35.67) 54.78,34.99 55.13,34.63 R264.1
PTC2/MII_RMII_TXD0: length 103.8
  TOP w0.406: R260.2 57.25,35 57.25,35 v1(57.67,34.59) ; v1(102.98,63.82) 103.04,63.82 103.04,63.76 103.49,64.22 R102.2
  L6_INT_2 w0.191: v1(57.67,34.59) 59.25,34.59 60.7,33.14 61.12,33.14 61.2,33.06 61.64,33.06 61.74,33.16 61.74,33.68 61.83,33.77 61.96,33.77 62.05,33.68 62.05,33.16 62.15,33.06 62.28,33.06 62.37,33.16 62.37,33.68 62.46,33.77 62.59,33.77 62.69,33.68 62.69,33.16 62.78,33.06 67.57,33.06 67.66,33.16 67.66,33.33 67.75,33.42 67.89,33.42 67.98,33.33 67.98,33.16 68.07,33.06 68.2,33.06 68.3,33.16 68.3,33.33 68.39,33.42 68.52,33.42 68.61,33.33 68.61,33.16 68.71,33.06 68.84,33.06 68.93,33.16 68.93,33.33 69.02,33.42 69.16,33.42 69.25,33.33 69.25,33.16 69.34,33.06 70.88,33.06 70.97,33.16 70.97,33.81 71.06,33.9 71.19,33.9 71.29,33.81 71.29,33.16 71.38,33.06 71.51,33.06 71.6,33.16 71.6,33.81 71.7,33.9 71.83,33.9 71.92,33.81 71.92,33.16 72.02,33.06 72.15,33.06 72.24,33.16 72.24,33.81 72.33,33.9 72.46,33.9 72.56,33.81 72.56,33.16 72.65,33.06 72.78,33.06 72.87,33.16 72.87,33.81 72.97,33.9 73.1,33.9 73.19,33.81 73.19,33.16 73.29,33.06 73.42,33.06 73.51,33.16 73.51,33.81 73.6,33.9 73.73,33.9 73.83,33.81 73.83,33.16 73.92,33.06 74.05,33.06 74.14,33.16 74.14,33.81 74.24,33.9 74.37,33.9 74.46,33.81 74.46,33.16 74.56,33.06 74.69,33.06 74.78,33.16 74.78,33.81 74.87,33.9 75,33.9 75.1,33.81 75.1,33.16 75.19,33.06 75.32,33.06 75.41,33.16 75.41,33.81 75.51,33.9 75.64,33.9 75.73,33.81 75.73,33.16 75.83,33.06 75.96,33.06 76.05,33.16 76.05,33.81 76.14,33.9 76.27,33.9 76.37,33.81 76.37,33.16 76.46,33.06 76.59,33.06 76.68,33.16 76.68,33.81 76.78,33.9 76.91,33.9 77,33.81 77,33.16 77.1,33.06 77.23,33.06 77.32,33.16 77.32,33.81 77.41,33.9 77.54,33.9 77.64,33.81 77.64,33.16 77.73,33.06 77.86,33.06 77.95,33.16 77.95,33.81 78.05,33.9 78.18,33.9 78.27,33.81 78.27,33.16 78.37,33.06 79.53,33.06 80.56,34.1 81.12,34.1 81.22,34.19 81.22,34.38 81.31,34.48 81.44,34.48 81.54,34.38 81.54,34.19 81.63,34.1 81.76,34.1 81.85,34.19 81.85,34.38 81.95,34.48 82.08,34.48 82.17,34.38 82.17,34.19 82.26,34.1 82.39,34.1 82.49,34.19 82.49,34.38 82.58,34.48 82.71,34.48 82.81,34.38 82.81,34.19 82.9,34.1 83.03,34.1 83.12,34.19 83.12,34.38 83.22,34.48 83.35,34.48 83.44,34.38 83.44,34.19 83.53,34.1 83.85,34.1 85.03,35.28 85.03,35.41 84.83,35.61 84.83,35.74 84.93,35.83 85.06,35.83 85.26,35.64 85.39,35.64 85.48,35.73 85.48,35.86 85.28,36.06 85.28,36.19 85.38,36.28 85.51,36.28 85.71,36.09 85.84,36.09 85.93,36.18 85.93,36.31 85.73,36.51 85.73,36.64 85.83,36.73 85.96,36.73 86.16,36.53 86.29,36.53 86.38,36.63 86.38,36.76 86.18,36.96 86.18,37.09 86.27,37.18 86.41,37.18 86.6,36.98 86.74,36.98 86.83,37.08 86.83,37.21 86.63,37.41 86.63,37.54 86.72,37.63 86.86,37.63 87.05,37.43 87.19,37.43 87.28,37.53 87.28,37.66 87.08,37.86 87.08,37.99 87.17,38.08 87.3,38.08 87.5,37.88 87.63,37.88 87.73,37.97 87.73,38.11 87.53,38.3 87.53,38.44 87.62,38.53 87.75,38.53 87.95,38.33 88.08,38.33 88.18,38.42 88.18,38.55 87.98,38.75 87.98,38.89 88.07,38.98 88.2,38.98 88.4,38.78 88.53,38.78 88.63,38.87 88.63,39 88.43,39.2 88.43,39.33 88.52,39.43 88.65,39.43 88.85,39.23 88.98,39.23 89.07,39.32 89.07,39.45 88.88,39.65 88.88,39.78 88.97,39.88 89.1,39.88 89.3,39.68 89.43,39.68 89.52,39.77 89.52,39.9 89.33,40.1 89.33,40.23 89.42,40.33 89.55,40.33 89.75,40.13 89.88,40.13 89.97,40.22 89.97,40.35 89.77,40.55 89.77,40.68 89.87,40.77 90,40.77 90.2,40.58 90.33,40.58 91.78,42.03 91.78,46.42 93.04,47.68 93.04,47.7 98.21,52.87 99.04,52.87 99.14,52.96 99.14,53.21 99.23,53.31 99.36,53.31 99.46,53.21 99.46,52.96 99.55,52.87 99.87,52.87 101.33,54.33 101.33,54.46 104.38,57.51 104.38,60.95 104.03,61.3 104.03,61.43 104.25,61.66 104.25,61.79 104.16,61.88 104.02,61.88 103.8,61.66 103.67,61.66 102.98,62.35 v1(102.98,63.82)
PTC2/MII_RMII_TXD0/QSPI_A_IO3: length 54.1
  TOP w0.16: U7.43 v1(59.45,59.43) ; U8.51 54.2,61.44 53.99,61.22 v1(53.53,61.22)
  TOP w0.406: v1(45.91,37.77) 46.01,37.68 R249.1
  L3_INT_1 w0.191: v1(45.91,37.77) 45.91,37.2 46.64,36.47 46.64,35.48 46.01,34.85 45.29,34.85 42.78,37.37 42.32,37.37 40.49,39.19 40.49,41.61 39.65,42.46 39.65,48.23 39.48,48.4 39.48,50.58 39.94,51.04 39.94,51.71 41.12,52.89 42.31,52.89 46.65,57.23 50.6,57.23 v1(51.32,57.95)
  L6_INT_2 w0.191: v1(51.32,57.95) 52.74,59.37
  L6_INT_2 w0.203: v1(53.53,61.22) 53.53,60.16 52.74,59.37
  BOTTOM w0.16: v1(59.45,59.43) 57.33,59.43 55.36,61.4 54.16,61.4 53.99,61.22 v1(53.53,61.22)
PTC2/MII_RMII_TXD0/QSPI_A_IO3_1: length 3.6
  TOP w0.229: 48.09,37.68 v1(48.86,37.68) 48.86,36.99 49.44,36.41 U16.11
  BOTTOM w0.229: v1(48.86,37.68) 48.09,37.68
PTC2/MII_RMII_TXD0/QSPI_A_IO3__: length 4.6
  TOP w0.279: R260.1 R254.1 v1(54.67,36.66) 54.42,36.41 U16.4
  BOTTOM w0.279: v1(54.67,36.66) 55.17,36.16 55.17,36.06 R260.1
PTC2/QSPI_A_IO3: length 48.4
  TOP w0.406: R254.2 56.86,36.41 57.49,36.41 v1(57.65,36.26)
  L6_INT_2 w0.191: v1(57.65,36.26) 54.94,36.26 54.87,36.19 53.31,36.19 52.4,35.28 48.59,35.28 48.51,35.36 47.22,35.36 46.72,34.85 41.18,34.85 41.01,34.69 38.16,34.69 v1(37.48,35.37)
  BOTTOM w0.406: v1(37.48,35.37) 37.48,32.19 36.92,31.63 33.17,31.63 32.72,32.09 31.18,32.09 30.19,33.08 22.67,33.08 21.81,33.94 21.81,35.32 21.65,35.48 21.02,35.48 20.87,35.63 20.87,35.86 21.02,36.01 21.65,36.01 22.17,36.54 22.44,36.54 R586.1
PTC3/MII_TX_ER: length 119.7
  TOP w0.406: R55.1 v1(121.25,72.86) ; R212.2 40.4,43.09 40.4,43.09 40.53,42.96 v1(42.08,42.96)
  L6_INT_2 w0.191: v1(121.25,72.86) 120.77,72.86 116.4,77.23 101.77,77.23 99.27,74.72 98.23,74.72 95.04,71.54 95.04,69.8 98.72,66.13 98.72,65.36 99.3,64.78 99.3,59.85 96.63,57.17 96.63,57.16 96.16,56.7 93.74,56.7 88.44,51.4 88.25,51.21 88.25,44.29 85.01,41.05 84.1,41.05 84.08,41.03 56.57,41.03 55.99,40.44 50.87,40.44 49.12,42.19 46.12,42.19 45.64,41.71 45.64,41.63 45.15,41.15 43.41,41.15 42.08,42.49 v1(42.08,42.96)
PTC3/MII_TX_ER/QSPI_A_CS/QSPI_1: length 3.5
  TOP w0.279: R175.2 38.82,51.78 v1(38.82,51.5) 38.57,51.24 U11.11
  BOTTOM w0.279: R175.2 38.82,51.78 v1(38.82,51.5)
PTC3/MII_TX_ER/QSPI_A_CS/QSPI_2: length 29
  TOP w0.16: U7.42 v1(58.98,59.93) ; U8.50 v1(54.65,61.94)
  TOP w0.406: R175.1 v1(38.19,55.61)
  L3_INT_1 w0.191: v1(38.19,55.61) 38.19,56.09 44.04,61.94 52.74,61.94
  L3_INT_1 w0.203: 52.74,61.94 v1(54.65,61.94)
  BOTTOM w0.16: v1(58.98,59.93) 57.47,59.93 55.46,61.94 v1(54.65,61.94)
PTC3/MII_TX_ER/QSPI_A_CS/QSPI_B: length 4.9
  TOP w0.279: U11.4 38.57,46.32 v1(38.85,46.04) 38.85,45.65 R212.1 R213.1
  BOTTOM w0.279: R213.1 39.61,46.04 v1(38.85,46.04)
PTC3/QSPI_A_CS: length 48.5
  TOP w0.406: R213.2 41.08,43.55 42.22,43.55 v1(42.48,43.55)
  L6_INT_2 w0.191: v1(37.73,38.75) 37.73,39.22 37.5,39.45 37.5,40.4 37.6,40.49 37.94,40.49 38.03,40.4 38.03,39.98 38.12,39.89 38.25,39.89 38.35,39.98 38.35,40.4 38.44,40.49 38.57,40.49 38.66,40.4 38.66,39.98 38.76,39.89 38.89,39.89 38.98,39.98 38.98,40.4 39.07,40.49 41.27,40.49 41.36,40.58 41.36,40.71 41.27,40.81 37.6,40.81 37.5,40.9 37.5,41.58 37.81,41.9 40.25,41.9 40.47,42.12 40.47,42.25 40.14,42.59 40,42.59 39.76,42.34 39.63,42.34 39.54,42.44 39.54,42.57 39.78,42.81 39.78,42.94 39.69,43.04 39.56,43.04 39.31,42.79 39.18,42.79 39.09,42.89 39.09,43.02 39.33,43.26 39.33,43.39 39.24,43.48 39.11,43.48 38.86,43.24 38.73,43.24 38.64,43.34 38.64,43.47 38.88,43.71 38.88,43.84 38.66,44.07 38.66,44.2 38.75,44.29 38.88,44.29 40.7,42.48 40.83,42.48 40.92,42.57 40.92,42.7 39.1,44.52 39.1,44.65 39.2,44.74 39.33,44.74 41.14,42.92 41.28,42.92 41.37,43.02 41.37,43.15 39.55,44.97 39.55,45.1 39.65,45.19 39.78,45.19 40.3,44.67 40.43,44.67 40.66,44.89 40.66,45.02 40.16,45.52 40.16,45.65 40.26,45.74 40.39,45.74 40.88,45.25 41.01,45.25 41.61,45.85 41.74,45.85 41.83,45.75 41.83,45.62 40.66,44.44 40.66,44.31 40.75,44.22 40.88,44.22 42.06,45.4 42.19,45.4 42.28,45.3 42.28,45.17 41.1,43.99 41.1,43.86 41.59,43.37 41.73,43.37 41.9,43.55 v1(42.48,43.55)
  BOTTOM w0.406: R581.1 37.55,38.82 37.58,38.8 37.73,38.8 v1(37.73,38.75)
PTC4/FTM1_CH0/RTC_CLKOUT/JTAG_T: length 174.1
  TOP w0.16: U7.140 v1(77.63,60.43) ; U8.169 v1(82.92,60.94)
  TOP w0.406: R298.2 35.42,15.62 36.5,16.7 38.01,16.7 38.42,16.29 v1(38.42,15.1)
  L3_INT_1 w0.191: v1(97.5,69) 97.5,68.26 96.46,67.23 96.46,64.42 97.36,63.52 97.36,63.06 97.09,62.78 96.92,62.78 95.08,60.94 83.93,60.94
  L3_INT_1 w0.203: v1(82.92,60.94) 83.93,60.94
  L6_INT_2 w0.191: v1(38.42,15.1) 45.76,15.1 47.38,13.48 97.82,13.48 106.62,22.27 106.62,53.57 108.21,55.16 108.21,69.23 103.74,73.7 100.65,73.7 97.54,70.59 97.54,69.87 97.5,69.82 v1(97.5,69)
  BOTTOM w0.16: v1(77.63,60.43) 79.23,60.43 79.73,60.94 v1(82.92,60.94)
  BOTTOM w0.406: v1(97.5,69) 96.91,68.41 R510.2
PTC5/FTM2_CH0/RTC_CLKOUT/JTAG_T: length 26.9
  TOP w0.16: U8.168 v1(82.44,60.44) ; U7.139 v1(78.1,59.93)
  L3_INT_1 w0.191: 83.93,60.44 95.03,60.44 97.05,62.46 97.22,62.46 97.68,62.93 97.68,63.91 v1(96.94,64.65)
  L3_INT_1 w0.203: 83.93,60.44 v1(82.44,60.44)
  BOTTOM w0.16: v1(82.44,60.44) 81.93,59.93 v1(78.1,59.93)
  BOTTOM w0.406: v1(96.94,64.65) 96.13,63.84 R516.2
PTC6/LPUART1_RX/CAN1_RX/FTM3_CH: length 139.9
  TOP w0.16: U7.118 v1(77.63,49.43) ; v1(82.87,48.43) U8.144
  L3_INT_1 w0.191: v1(74.66,30.92) 78.06,34.32 78.74,34.32 79.39,34.98 79.39,37.29 80.72,38.62
  L3_INT_1 w0.203: v1(77.63,49.43) 78.28,49.43 79.34,48.38 79.34,41.92 80.93,40.33 80.93,38.83 80.72,38.62
  BOTTOM w0.16: v1(77.63,49.43) 80.16,49.43 81.16,48.43 v1(82.87,48.43)
  BOTTOM w0.203: J6.11 83.78,79.22 85,78 85,77.17 87.1,75.07 87.4,75.07 89.09,73.38 89.09,68.33 89.09,68.32 89.09,67.5 89.09,67.5 89.09,67.23 88.84,66.98 88.84,57.94 88.84,57.94 88.84,57.12 88.84,57.11 88.84,56.84 88.53,56.54 88.53,56.49 85.28,53.24 85.28,51.45 84.42,50.58 84.42,49.39 83.45,48.43 v1(82.87,48.43)
  BOTTOM w0.406: R627.2 21.5,11.87 v1(21.65,11.72) 23.43,9.94 28.13,9.94 29.02,10.83 32.75,10.83 33.57,10.02 50.42,10.02 56.32,15.92 56.32,20.56 57.54,21.78 71.56,21.78 74.92,25.13 74.92,30.67 v1(74.66,30.92)
PTC7/LPUART1_TX/CAN1_TX/FTM3_CH: length 135.8
  TOP w0.16: v1(82.44,47.9) 82.41,47.93 U8.143 ; U7.117 v1(78.1,48.93)
  L3_INT_1 w0.191: v1(22.44,16.65) 23.62,15.47 23.62,12.56 25.66,10.52 27.84,10.52 28.05,10.73 42.81,10.73 48.3,16.22 55.23,16.22 58.81,19.8 66.73,19.8 72.17,25.24 72.17,29.76 77.38,34.97 78.47,34.97 78.75,35.25 78.75,37.87 79.5,38.62
  L3_INT_1 w0.203: 79.5,38.62 80.22,39.34 80.22,40.03 78.6,41.65 78.6,45.11 78.26,45.45 77.9,45.45 77.54,45.81 76.72,45.81 76.44,46.09 76.44,47.93 77.45,48.93 v1(78.1,48.93)
  BOTTOM w0.16: v1(82.44,47.9) 81.06,47.9 80.02,48.93 v1(78.1,48.93)
  BOTTOM w0.203: v1(82.44,47.9) 83.42,47.9 84.95,49.42 84.95,50.33 85.81,51.19 85.81,53.31 88.86,56.36 88.86,56.4 89.17,56.7 89.17,56.98 89.17,58.07 89.17,58.07 89.17,66.84 89.42,67.09 89.42,67.37 89.42,68.46 89.42,68.46 89.42,73.52 88.86,74.08 88.86,74.94 87.64,76.15 87.64,78.65 J6.8
  BOTTOM w0.279: v1(22.44,16.65) 22.95,16.14 22.95,16.01
PTC8/LPUART1_RX: length 156.1
  TOP w0.16: U7.81 v1(63.79,44.12) ; 63.29,40.98 v1(63.29,39.32)
  TOP w0.305: v1(19.93,9.73) 19.93,11.2 20.36,11.63 R305.2
  TOP w0.406: R34.1 61.79,75.49 61.73,75.45 61.73,75.47 v1(61.67,75.47)
  L3_INT_1 w0.191: 62.79,38.62 62.15,37.99 62.15,33.06 59.37,30.27 55.39,30.27 54.6,29.48 54.6,28.91 53.46,27.77 50.35,27.77 49.66,27.08 49.66,25.12 48.25,23.71 48.25,23.37 47.46,22.58 45.37,22.58 40.55,17.77 40.55,13.32 v1(39.69,12.46)
  L3_INT_1 w0.203: 62.79,38.62 63.29,39.12 v1(63.29,39.32)
  L6_INT_2 w0.191: v1(19.93,9.73) 37.72,9.73 39.69,11.69 v1(39.69,12.46)
  L6_INT_2 w0.203: v1(83.63,73.19) 82.56,74.25 82.56,80.21 81.7,81.07 75.34,81.07 75.02,81.39 67.88,81.39 67.07,80.58 67.07,79.06 63.48,75.47 v1(61.67,75.47)
  BOTTOM w0.16: v1(63.79,44.12) 63.79,40.9 63.29,40.4 v1(63.29,39.32)
  BOTTOM w0.203: v1(83.63,73.19) 83.97,73.53 86.92,73.53 87.54,72.91 87.54,67.55 87.52,67.52 87.52,57.63 82.78,52.89 81.72,52.89 79.6,50.77 77.75,50.77 76.88,49.9 69.91,49.9 65.23,45.22 64.24,45.22 63.79,44.78 v1(63.79,44.12)
PTC9/LPUART1_TX: length 141.8
  TOP w0.16: 62.79,40.98 v1(62.79,39.79) ; U7.80 v1(63.29,44.59)
  TOP w0.406: R14.1 v1(59.91,76.25)
  L3_INT_1 w0.191: v1(57.16,30.74) 59.17,30.74 61.84,33.41 61.84,38.17 62.28,38.62
  L3_INT_1 w0.203: 62.28,38.62 62.79,39.12 v1(62.79,39.79)
  L6_INT_2 w0.191: v1(49.42,18.45) 48.98,18.88 46.49,18.88 45.3,17.69 34.57,17.69 33.89,18.37 30.13,18.37 29.35,17.59 27.11,17.59 26.09,16.56 v1(24.57,16.56) ; v1(63.29,44.59) 67.93,49.24 76.72,49.24 78.52,51.03 78.52,53.8 77.15,55.17 74.02,55.17 73.4,55.79 73.4,59.11 75.85,61.55 76.37,61.55 76.72,61.91 77.33,61.91 77.79,61.45 78.3,61.45 79.32,62.48 v1(79.32,64.67) ; v1(59.91,76.25) 61.47,74.69 63.49,74.69 67.65,78.85 73.76,78.85 74.97,77.64 74.97,77.07 75.73,76.31 76.08,76.31 77.41,74.99 v1(77.41,74.51)
  BOTTOM w0.16: v1(62.79,39.79) 62.98,39.97 62.98,40.53 63.29,40.85 v1(63.29,44.59)
  BOTTOM w0.203: 82.08,69.05 82.08,67.42 v1(79.32,64.67)
  BOTTOM w0.406: 82.08,69.05 82.08,69.84 v1(77.41,74.51) ; v1(49.42,18.45) 49.83,18.86 49.83,20.36 50.94,21.47 55.46,21.47 57.16,23.18 v1(57.16,30.74) ; v1(24.57,16.56) 24.43,16.56 R619.2
PTC10/FTM3_CH4/TRGMUX_IN11: length 55.5
  TOP w0.16: U7.75 v1(60.79,44.12) ; 60.29,40.98 v1(60.29,39.32)
  L6_INT_2 w0.203: v1(52.74,60.92) 52.74,60.44 47.89,55.59 47.89,48.62 52.57,43.94 53.27,43.94 53.73,44.41 55.21,44.41 55.98,43.64 60.31,43.64 v1(60.79,44.12)
  BOTTOM w0.16: v1(60.29,39.32) 60.29,40.6 60.79,41.1 v1(60.79,44.12)
  BOTTOM w0.203: 53.84,69.05 52.74,67.96 v1(52.74,60.92)
  BOTTOM w0.406: J1.10 55.84,75.75 53.84,73.75 53.84,69.05
PTC11/FTM3_CH5/FTM4_CH2/TRGMUX_: length 57.1
  TOP w0.16: 59.28,40.98 v1(59.28,39.32) ; U7.74 v1(60.29,44.59)
  TOP w0.406: J1.7 57.04,76.08 49.26,76.08 48.3,75.12 v1(48.3,74.53)
  L3_INT_1 w0.191: v1(48.3,74.53) 48.64,74.2 49.04,74.2 54.19,69.05
  L3_INT_1 w0.203: v1(60.29,44.59) 60.28,44.61 59.59,44.61 59.43,44.45 58.78,44.45 58.5,44.73 58.5,65.24 55.92,67.83 55.41,67.83 54.19,69.05
  BOTTOM w0.16: v1(59.28,39.32) 59.28,40.74 60.29,41.75 v1(60.29,44.59)
PTC12: length 10.7
  TOP w0.16: U7.71 v1(59.52,45.43) ; U8.84 v1(54.65,44.92)
  BOTTOM w0.16: v1(59.52,45.43) 55.15,45.43 v1(54.65,44.92)
  BOTTOM w0.203: R565.2 R567.2 60.36,46.06 59.73,45.43 v1(59.52,45.43)
PTC12/BTN0: length 96.3
  TOP w0.406: R306.2 C109.1 v1(93.66,14.13)
  L3_INT_1 w0.191: v1(47.13,23.38) 47.13,25.41 48.71,26.99 48.71,32.53 50.32,34.14 50.32,43.66 v1(51.96,45.3)
  L6_INT_2 w0.191: v1(63.94,46.8) 62.83,47.91 59.63,47.91 59.18,47.45 54.11,47.45 v1(51.96,45.3) ; v1(93.66,14.13) 93.19,14.13 92.86,13.8 50.48,13.8 47.13,17.16 v1(47.13,18.07)
  BOTTOM w0.203: v1(63.94,46.8) 63.89,46.75 TP507.1 62.88,47.03 R565.1
  BOTTOM w0.406: v1(47.13,23.38) v1(47.13,18.07)
PTC12/FTM3_CH6/FTM2_CH6/LPUART2: length 53.2
  L3_INT_1 w0.191: J6.5 87.75,78.86 87.75,73.91 v1(86.8,72.96)
  BOTTOM w0.203: v1(86.8,72.96) 87.21,72.55 87.21,67.69 87.19,67.66 87.19,57.8 83.47,54.09 81.9,54.09 78.94,51.12 77.6,51.12 77.39,50.91 69.92,50.91 65.06,46.06 R567.1
PTC13: length 12.1
  TOP w0.16: U7.70 v1(58.98,45.93) ; U8.81 v1(54.18,46.43)
  BOTTOM w0.16: v1(58.98,45.93) 55.59,45.93 55.1,46.43 v1(54.18,46.43)
  BOTTOM w0.203: v1(58.98,45.93) 59.64,45.93 60.44,46.73 60.44,47.38 R562.2 R561.2
PTC13/BTN1: length 78.9
  TOP w0.406: v1(97.62,13.96) C110.1 R307.2
  L3_INT_1 w0.191: v1(84.67,30.72) 87.7,33.75 87.7,43.95 87.69,43.96 87.69,53.11 85.57,55.24 85.25,55.24 v1(84.59,55.89)
  BOTTOM w0.203: 83.93,55.24 82.21,55.24 79.34,52.36 77.84,52.36 76.88,51.39 66.59,51.39 TP506.1 63.13,47.99 R562.1
  BOTTOM w0.406: v1(84.59,55.89) 83.93,55.24 ; v1(97.62,13.96) 96.18,13.96 85.1,25.03 85.1,30.29 v1(84.67,30.72)
PTC13/FTM3_CH7/FTM2_CH7/LPUART2: length 52
  L3_INT_1 w0.191: v1(86.73,69.89) 92.51,75.67 92.51,78.86 J6.2
  BOTTOM w0.191: R561.1 63.56,48.96 66.38,51.78 76.76,51.78 77.7,52.71 78.2,52.71 81.33,55.84 82.54,55.84 83.11,56.41
  BOTTOM w0.203: 83.11,56.41 83.93,57.24
  BOTTOM w0.406: v1(86.73,69.89) 86.73,60.03 83.93,57.24
PTC14/FTM1_CH2/LPSPI2_PCS0/ADC0: length 55.4
  TOP w0.16: U8.70 v1(54.65,51.93) ; U7.61 v1(60.69,50.43)
  TOP w0.406: v1(78.27,35.44) 79.71,35.44 83.19,31.96 87.31,31.96 88.86,30.41 J5.13
  L3_INT_1 w0.191: 79,38.62 78.27,37.89 v1(78.27,35.44)
  L3_INT_1 w0.203: 79,38.62 79.86,39.48 79.86,39.88 78.19,41.55 78.19,44.12 77.6,44.71 77.05,44.71 76.01,45.76 64.3,45.76 60.69,49.37 v1(60.69,50.43)
  BOTTOM w0.16: v1(54.65,51.93) 55.56,51.93 57.06,50.43 v1(60.69,50.43)
PTC15/FTM1_CH3/LPSPI2_SCK/QSPI_: length 75.7
  TOP w0.16: U7.59 v1(59.45,51.43) ; U8.67 v1(54.18,53.43)
  L3_INT_1 w0.191: 52.74,53.43 50.71,53.43 47.89,50.61 47.89,45.25 46.7,44.05 46.7,40.85 46.6,40.75 46.6,39.42 47.05,38.97 47.05,37.4 47.66,36.8 47.66,35.75 48.4,35.01 48.4,34.51 46.89,33.01 v1(46.89,28.74)
  L3_INT_1 w0.203: v1(54.18,53.43) 52.74,53.43
  L6_INT_2 w0.191: v1(46.89,28.74) 46.89,28.26 46.8,28.17 46.8,26.5 50.31,22.99 53.76,22.99 54.41,23.65 54.41,24.66 55.26,25.51 58.52,25.51 59.81,24.21 59.81,23.65 60.47,22.99 69.98,22.99 J5.2
  BOTTOM w0.16: v1(59.45,51.43) 57.46,51.43 55.46,53.43 v1(54.18,53.43)
PTC16/MII_RMII_RX_ER: length 157.6
  TOP w0.406: R195.2 42.18,49.52 v1(41.47,48.8) ; R61.1 v1(121.22,71.84)
  L6_INT_2 w0.191: v1(41.47,48.8) 41.47,47.98 38.38,44.89 34.01,44.89 30.09,40.97 30.09,37.33 32.18,35.24 35.09,35.24 36.4,33.93 41.15,33.93 41.33,34.1 46.53,34.1 47.05,33.58 48.88,33.58 49.43,34.13 54.58,34.13 55.83,35.38 60.73,35.38 61.7,34.41 65.3,34.41 66.19,35.3 74.32,35.3 76.33,37.31 82.6,37.31 83.65,38.36 85.47,38.36 90.48,43.37 90.48,46.91 91.77,48.21 91.77,48.22 98.12,54.58 99.78,54.58 100.06,54.85 100.06,54.98 103.11,58.04 103.11,59.9 101.87,61.14 101.87,65.47 102.17,65.76 102.17,66.35 101.65,66.86 98.44,66.86 95.36,69.94 95.36,71.41 98.36,74.41 99.45,74.41 101.96,76.92 116.15,76.92 v1(121.22,71.84)
PTC16/MII_RMII_RX_ER/QSPI_B_I_1: length 31.8
  TOP w0.16: U8.65 v1(54.18,54.43) ; U7.57 v1(59.45,52.43)
  TOP w0.406: R230.1 v1(43.6,39.11)
  L3_INT_1 w0.191: v1(43.6,39.11) 44.48,40 44.48,42.83 47.24,45.58 47.24,50.86 50.81,54.43 52.74,54.43
  L3_INT_1 w0.203: 52.74,54.43 v1(54.18,54.43)
  BOTTOM w0.16: v1(59.45,52.43) 57.41,52.43 55.41,54.43 v1(54.18,54.43)
